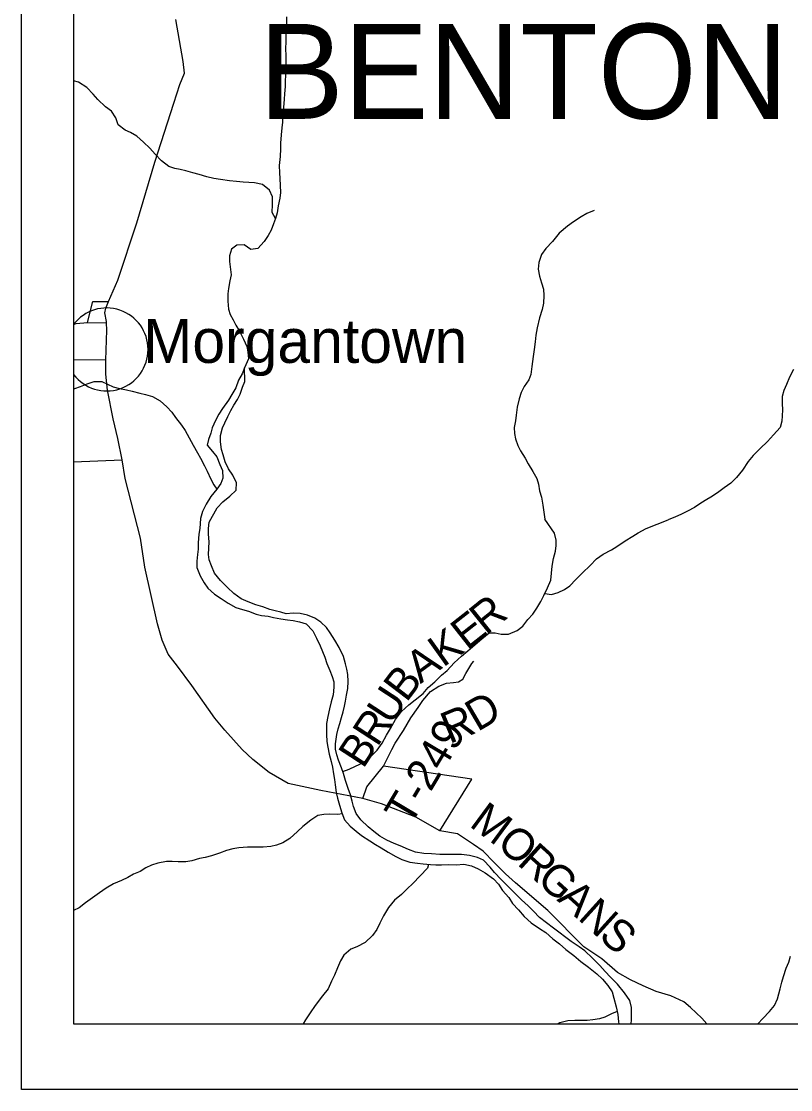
# Model space of a CAD drawing. Extents: x 0 to 34, y 0 to 22.
# Drawn here: x 2.106 to 3.486, y 13.882 to 15.799 of the extents above; entities that cross this region are included whole.
import ezdxf

# ---------------------------------------------------------------- set-up
doc = ezdxf.new("R2010")
doc.units = 0
for name, color, linetype in [('Default', 7, 'Continuous'), ('GM_X_County_Road', 7, 'Continuous'), ('GM_X_County_Road_Text', 7, 'Continuous'), ('GM_X_Minor_River', 7, 'Continuous'), ('GM_X_Township_Road', 7, 'Continuous'), ('GM_X_Township_Road_Text', 7, 'Continuous'), ('GM_X_Township_Text', 7, 'Continuous'), ('GM_X_Unincorporated_Location', 7, 'Continuous'), ('GM_X_Unincorporated_Text', 7, 'Continuous'), ('SH_Cut_Line', 7, 'Continuous')]:
    doc.layers.add(name, color=color, linetype=linetype)

msp = doc.modelspace()

# ---------------------------------------------------------------- linework, layer by layer
at = {"layer": 'Default'}
msp.add_lwpolyline([(9.087, 13.8822), (2.1062, 13.8822), (2.1062, 20.9054), (9.087, 20.9054)], close=True, dxfattribs=at)
msp.add_lwpolyline([(2.2, 19.4329), (2.2, 14), (4.485, 14)], dxfattribs=at)
at = {"layer": 'GM_X_County_Road'}
msp.add_line((2.2577, 15.1912), (2.2, 15.1918), dxfattribs=at)
msp.add_lwpolyline([(3.3359, 14), (3.3268, 14.0106), (3.3065, 14.0298), (3.2945, 14.0395), (3.2711, 14.0504), (3.2447, 14.0583), (3.2217, 14.0684), (3.1987, 14.0793), (3.1753, 14.0921), (3.1472, 14.1168), (3.1152, 14.1384), (3.0503, 14.2034), (2.9925, 14.2535), (2.9749, 14.2696), (2.9546, 14.29), (2.9347, 14.31), (2.9174, 14.322), (2.8885, 14.3409), (2.8571, 14.3467), (2.8141, 14.371), (2.7522, 14.3953), (2.719, 14.4048), (2.6434, 14.419), (2.6101, 14.4262), (2.5848, 14.4318), (2.5505, 14.4512), (2.5215, 14.4747), (2.502, 14.4928), (2.471, 14.5274), (2.453, 14.5485), (2.4123, 14.6071), (2.3862, 14.642), (2.3697, 14.6634), (2.3586, 14.6886), (2.3502, 14.718), (2.3278, 14.8197), (2.32, 14.8715), (2.2924, 14.9786), (2.2872, 15.0122), (2.2791, 15.0506), (2.2708, 15.0861), (2.2607, 15.1371), (2.258, 15.166), (2.2577, 15.1912), (2.2594, 15.2447), (2.2589, 15.2582), (2.2588, 15.2603), (2.256, 15.2759), (2.2576, 15.2846), (2.2628, 15.2966), (2.2793, 15.3345), (2.3133, 15.4373), (2.3455, 15.5463), (2.3795, 15.6522), (2.3905, 15.6859), (2.3986, 15.7063), (2.3966, 15.7268), (2.3834, 15.8025)], dxfattribs=at)
at = {"layer": 'GM_X_Minor_River'}
msp.add_line((3.1776, 14.0036), (3.1782, 14), dxfattribs=at)
for points in [[(2.5821, 15.8073), (2.5817, 15.7971), (2.5809, 15.7849), (2.5805, 15.7735), (2.5805, 15.7629), (2.5801, 15.7496), (2.5805, 15.7378), (2.5805, 15.7172), (2.5801, 15.7024), (2.5797, 15.6918), (2.5793, 15.6823), (2.5782, 15.6689), (2.5774, 15.6591), (2.5763, 15.6442), (2.5755, 15.6317), (2.5748, 15.6184), (2.5736, 15.6077), (2.5725, 15.5956), (2.5713, 15.5807), (2.5709, 15.5701), (2.5702, 15.5568), (2.5686, 15.5404), (2.5694, 15.5275), (2.5698, 15.5172), (2.5705, 15.5047), (2.5709, 15.4918), (2.5697, 15.4819), (2.5671, 15.4678), (2.5648, 15.4553), (2.5621, 15.445), (2.5587, 15.4355), (2.5545, 15.4245), (2.5492, 15.415), (2.5416, 15.4039), (2.5303, 15.3914), (2.5177, 15.3899), (2.5056, 15.3982), (2.4927, 15.3975), (2.4829, 15.3903), (2.4794, 15.3781), (2.4794, 15.3682), (2.4809, 15.3587), (2.4824, 15.3443), (2.4802, 15.3336), (2.4775, 15.3199), (2.4767, 15.31), (2.4767, 15.2967), (2.4775, 15.2827), (2.4805, 15.2728), (2.4862, 15.2633), (2.4911, 15.2538), (2.4976, 15.2431), (2.5048, 15.2287), (2.5104, 15.2157), (2.5127, 15.2059), (2.5135, 15.1937), (2.5066, 15.1773)], [(2.5621, 15.445), (2.5561, 15.456), (2.5569, 15.4705), (2.5565, 15.4842), (2.5512, 15.4963), (2.539, 15.5062), (2.5243, 15.5093), (2.514, 15.51), (2.5042, 15.5104), (2.492, 15.5115), (2.4795, 15.5127), (2.4632, 15.515), (2.4514, 15.5172), (2.4389, 15.5203), (2.4253, 15.5245), (2.4139, 15.5275), (2.401, 15.5309), (2.3908, 15.5332), (2.3813, 15.5351), (2.3707, 15.5385), (2.3578, 15.5488), (2.346, 15.561), (2.3366, 15.5712), (2.3256, 15.5823), (2.3134, 15.5929), (2.3017, 15.5998), (2.2922, 15.6039), (2.2797, 15.6131), (2.2755, 15.6256), (2.2679, 15.6378), (2.2573, 15.6454), (2.2433, 15.6587), (2.235, 15.6682), (2.2236, 15.6804), (2.2088, 15.6899), (2.2, 15.692)], [(3.1337, 15.4599), (3.1208, 15.4542), (3.1105, 15.4485), (3.0969, 15.4393), (3.0859, 15.4317), (3.0711, 15.4188), (3.0589, 15.4043), (3.0472, 15.3914), (3.0392, 15.3808), (3.0343, 15.3663), (3.0335, 15.3542), (3.0358, 15.3416), (3.0395, 15.3298), (3.0426, 15.3184), (3.0437, 15.3074), (3.0426, 15.2933), (3.0403, 15.2819), (3.0357, 15.2671), (3.0312, 15.2492), (3.0289, 15.2359), (3.0277, 15.2241), (3.0262, 15.2101), (3.0243, 15.1975), (3.022, 15.18), (3.0201, 15.1656), (3.0167, 15.1557), (3.0084, 15.1439), (3.0027, 15.1333), (2.9992, 15.1215), (2.9958, 15.1067), (2.9939, 15.0926), (2.9924, 15.0823), (2.9901, 15.0702), (2.9909, 15.0595), (2.9924, 15.05), (2.9965, 15.0382), (3.0015, 15.0287), (3.0098, 15.0154), (3.0151, 15.0051), (3.0238, 14.9915), (3.0306, 14.9785), (3.0337, 14.9683), (3.0359, 14.9569), (3.039, 14.9451), (3.0416, 14.931), (3.0435, 14.9181), (3.0454, 14.9055)], [(2.5066, 15.1773), (2.5021, 15.1667), (2.496, 15.1549), (2.4911, 15.1416), (2.4839, 15.1294), (2.4778, 15.1192), (2.4672, 15.1043), (2.4607, 15.0941), (2.4542, 15.0827), (2.4485, 15.0697), (2.4459, 15.0602), (2.4421, 15.0485), (2.4394, 15.0386), (2.4493, 15.0272), (2.4569, 15.0178), (2.4621, 15.0039), (2.4671, 14.9929), (2.4675, 14.9796), (2.464, 14.9698), (2.4568, 14.9599), (2.4462, 14.9462), (2.4379, 14.9329), (2.4314, 14.9196), (2.4276, 14.907)], [(2.443, 14.9003), (2.4572, 14.9264), (2.4674, 14.9371), (2.48, 14.9473), (2.4917, 14.958), (2.4921, 14.9709), (2.4853, 14.9846), (2.4777, 14.996), (2.472, 15.0089), (2.4682, 15.0211), (2.4652, 15.031), (2.4637, 15.0443), (2.4637, 15.0557), (2.4671, 15.0694), (2.4709, 15.0789), (2.4766, 15.0903), (2.4819, 15.1005), (2.4876, 15.1101), (2.4937, 15.1207), (2.4986, 15.1302), (2.5028, 15.1424), (2.507, 15.153), (2.5066, 15.1773)], [(3.4912, 15.1743), (3.4843, 15.1603), (3.4786, 15.1477), (3.4737, 15.1367), (3.471, 15.1257), (3.471, 15.1131), (3.4714, 15.1017), (3.471, 15.0911), (3.4702, 15.0816), (3.4672, 15.0705), (3.4554, 15.0572), (3.4444, 15.0454), (3.4315, 15.0325), (3.419, 15.0203), (3.4099, 15.0093), (3.4, 14.9937), (3.389, 14.9804), (3.3788, 14.9705), (3.3666, 14.9618), (3.3572, 14.955), (3.3458, 14.9473), (3.3329, 14.939), (3.3234, 14.9333), (3.3139, 14.9268), (3.301, 14.92), (3.2892, 14.9143), (3.2798, 14.9101), (3.2665, 14.9044)], [(2.2, 15.1404), (2.2024, 15.1405), (2.2123, 15.1439), (2.2244, 15.1485), (2.2366, 15.1526), (2.2506, 15.1526), (2.2711, 15.1435), (2.2821, 15.1401), (2.2946, 15.1378), (2.3052, 15.1355), (2.3185, 15.1321), (2.3287, 15.1294), (2.3412, 15.126), (2.3553, 15.118), (2.3674, 15.1074), (2.3761, 15.0975), (2.3829, 15.088), (2.3936, 15.0747), (2.4, 15.0648), (2.4072, 15.0519), (2.4144, 15.0386), (2.422, 15.0249), (2.4273, 15.015), (2.4349, 15.0013), (2.4394, 14.9918), (2.4462, 14.9774), (2.4515, 14.9675), (2.4568, 14.9599)], [(2.4276, 14.907), (2.4263, 14.8893), (2.4244, 14.8791), (2.4236, 14.8635), (2.4232, 14.8521), (2.4224, 14.8426), (2.4212, 14.8305), (2.4212, 14.8191), (2.4272, 14.8043), (2.434, 14.7917), (2.4407, 14.7818), (2.4524, 14.7712), (2.4645, 14.7635), (2.477, 14.7552), (2.491, 14.7475), (2.5027, 14.7437), (2.5136, 14.7406), (2.5272, 14.7356), (2.5371, 14.733), (2.5488, 14.7318), (2.5586, 14.7291), (2.5719, 14.7268), (2.5836, 14.7252), (2.5938, 14.7237), (2.6052, 14.7217), (2.6173, 14.7179), (2.629, 14.7057), (2.6357, 14.6924), (2.6421, 14.6787), (2.6466, 14.6681), (2.6504, 14.6582), (2.6541, 14.6468), (2.6594, 14.6343), (2.6639, 14.6236), (2.6665, 14.6141), (2.6668, 14.6042), (2.6653, 14.5906), (2.6622, 14.5781), (2.6591, 14.5652), (2.6561, 14.5519), (2.6537, 14.539), (2.6533, 14.5295), (2.6533, 14.5196), (2.6544, 14.5071), (2.6559, 14.4965), (2.6581, 14.4843), (2.6618, 14.471), (2.6645, 14.4611), (2.6663, 14.449), (2.6682, 14.4387), (2.6689, 14.4292), (2.6707, 14.4156), (2.673, 14.4053), (2.6767, 14.3924), (2.6808, 14.3787), (2.6861, 14.3665), (2.6963, 14.3548), (2.7065, 14.346), (2.7163, 14.3384), (2.731, 14.3288), (2.7412, 14.322), (2.7518, 14.3159), (2.7642, 14.3082), (2.7782, 14.3006), (2.7888, 14.2952), (2.8032, 14.2906), (2.8168, 14.2883), (2.827, 14.2872), (2.8399, 14.286), (2.8497, 14.2856), (2.8599, 14.2855), (2.8732, 14.2863), (2.886, 14.2858), (2.9, 14.2866), (2.9136, 14.2835), (2.9257, 14.2785), (2.9382, 14.2713), (2.9529, 14.2602), (2.962, 14.2507), (2.9691, 14.2396), (2.9808, 14.2267), (2.9872, 14.2164), (2.9978, 14.205), (3.008, 14.1928), (3.0208, 14.1814), (3.0355, 14.1711), (3.0468, 14.1642), (3.0597, 14.1528), (3.0718, 14.1437), (3.0831, 14.1338), (3.0974, 14.1231), (3.1099, 14.112), (3.1238, 14.1021), (3.1386, 14.0899), (3.1484, 14.0804), (3.1585, 14.069), (3.1657, 14.0576), (3.1687, 14.0466), (3.1732, 14.031), (3.1762, 14.0169), (3.1776, 14.0036)], [(3.2, 14), (3.2004, 14.0074), (3.2008, 14.0195), (3.2008, 14.0298), (3.1974, 14.0423), (3.1884, 14.056), (3.1756, 14.0712), (3.1631, 14.0842), (3.1537, 14.0941), (3.1439, 14.1051), (3.1307, 14.1184), (3.1171, 14.1314), (3.1066, 14.1382), (3.0926, 14.1482), (3.0828, 14.155), (3.0703, 14.1646), (3.0605, 14.1722), (3.048, 14.1817), (3.0356, 14.1909), (3.025, 14.2027), (3.0156, 14.2122), (3.0035, 14.2225), (2.9782, 14.248), (2.9669, 14.259), (2.9552, 14.2716), (2.9469, 14.2811), (2.9349, 14.2937), (2.9243, 14.2986), (2.9099, 14.3025), (2.8959, 14.304), (2.8566, 14.3041), (2.8418, 14.3053), (2.8282, 14.3061), (2.8134, 14.3081), (2.8006, 14.3131), (2.7859, 14.3195), (2.7749, 14.3238), (2.7617, 14.3299), (2.7492, 14.3371), (2.7383, 14.3451), (2.7284, 14.3539), (2.7149, 14.3661), (2.7066, 14.3779), (2.7021, 14.3904), (2.6998, 14.3999), (2.6968, 14.4109), (2.6927, 14.4227), (2.6878, 14.4368), (2.6841, 14.4493), (2.6807, 14.4596), (2.6751, 14.4733), (2.6721, 14.4831), (2.6699, 14.4934), (2.6699, 14.5029), (2.6718, 14.5192), (2.6745, 14.5298), (2.6772, 14.5393), (2.6807, 14.5499), (2.6833, 14.5602), (2.6856, 14.57), (2.6879, 14.5795), (2.6895, 14.5898), (2.6918, 14.6019), (2.6922, 14.6144), (2.6919, 14.6269), (2.69, 14.6368), (2.6874, 14.6463), (2.6841, 14.6592), (2.6762, 14.6756), (2.6686, 14.6885), (2.6604, 14.7018), (2.6536, 14.7117), (2.6434, 14.7209), (2.6324, 14.7281), (2.6196, 14.7338), (2.6063, 14.7365), (2.5939, 14.7373), (2.5814, 14.7359), (2.5715, 14.7389), (2.5617, 14.7412), (2.5519, 14.7439), (2.5394, 14.7485), (2.5269, 14.7523), (2.5133, 14.7573), (2.5005, 14.7627), (2.4873, 14.7726), (2.4759, 14.7833), (2.4635, 14.7958), (2.4529, 14.8091), (2.4473, 14.8221), (2.4432, 14.8327), (2.4417, 14.8426), (2.4425, 14.8536), (2.4429, 14.865), (2.4418, 14.879), (2.4419, 14.8893), (2.443, 14.9003)], [(2.6829, 14.4531), (2.694, 14.4573), (2.7057, 14.4625), (2.7186, 14.4686), (2.7311, 14.4784), (2.7444, 14.4913), (2.7532, 14.5038), (2.7612, 14.5185), (2.7684, 14.5303), (2.7772, 14.5466), (2.7882, 14.5606), (2.8011, 14.5727), (2.8128, 14.5814), (2.8269, 14.5931), (2.836, 14.6037), (2.8481, 14.6139), (2.8599, 14.6257), (2.8702, 14.634), (2.8823, 14.648), (2.896, 14.6601), (2.907, 14.6696), (2.9199, 14.6805), (2.9324, 14.6911), (2.9453, 14.7017), (2.9563, 14.7021), (2.9669, 14.6997), (2.9798, 14.6993), (2.9957, 14.7061), (3.0055, 14.7141), (3.015, 14.7258), (3.0234, 14.7356), (3.0306, 14.7462), (3.0379, 14.758), (3.0432, 14.7686), (3.05, 14.7826), (3.0558, 14.7963), (3.0573, 14.8088), (3.0581, 14.8213), (3.0608, 14.835), (3.0643, 14.8483), (3.0654, 14.8585), (3.0655, 14.8684), (3.0625, 14.8805), (3.0454, 14.9055)], [(3.0452, 14.7726), (3.0572, 14.7708), (3.0689, 14.7742), (3.0803, 14.7795), (3.0902, 14.7863), (3.1008, 14.7973), (3.1126, 14.8094), (3.1263, 14.8226), (3.1376, 14.8347), (3.1498, 14.8427), (3.1646, 14.851), (3.1744, 14.857), (3.1892, 14.8668), (3.2029, 14.8755), (3.2124, 14.8812), (3.2271, 14.8891), (3.2665, 14.9044)], [(2.6816, 14.377), (2.674, 14.3761), (2.6593, 14.3765), (2.6487, 14.3758), (2.6381, 14.3739), (2.6252, 14.366), (2.6111, 14.3543), (2.6016, 14.3452), (2.588, 14.3327), (2.5754, 14.3248), (2.5637, 14.321), (2.5535, 14.3187), (2.5402, 14.3173), (2.5118, 14.3174), (2.4963, 14.3163), (2.4853, 14.3144), (2.4744, 14.311), (2.4615, 14.3065), (2.4471, 14.302), (2.4357, 14.299), (2.4259, 14.2967), (2.4118, 14.293), (2.4012, 14.2908), (2.3876, 14.2908), (2.3766, 14.2916), (2.3664, 14.2916), (2.3509, 14.2886), (2.3395, 14.2849), (2.3293, 14.2803), (2.3191, 14.2739), (2.3073, 14.2686), (2.2971, 14.263), (2.2857, 14.2577), (2.2717, 14.2513), (2.2584, 14.2437), (2.2463, 14.2351), (2.2337, 14.2264), (2.2212, 14.2173), (2.2098, 14.2086), (2.2, 14.2037)], [(2.8367, 14.2863), (2.8345, 14.2795), (2.8216, 14.2659), (2.8083, 14.2523), (2.7985, 14.2428), (2.7878, 14.2322), (2.7757, 14.222), (2.765, 14.2088), (2.7559, 14.194), (2.7491, 14.1811), (2.7437, 14.1697), (2.7361, 14.1587), (2.7228, 14.1463), (2.708, 14.1387), (2.6974, 14.1342), (2.6845, 14.1232), (2.6784, 14.1134), (2.6731, 14.1009), (2.6678, 14.0876), (2.6628, 14.0766), (2.6563, 14.063), (2.6464, 14.0508), (2.6331, 14.0334), (2.6244, 14.0198), (2.616, 14.0073), (2.612, 14)], [(3.4274, 14), (3.4365, 14.0097), (3.4479, 14.0225), (3.4574, 14.0331), (3.4624, 14.0453), (3.4674, 14.0631), (3.4704, 14.0752), (3.4731, 14.0851), (3.4781, 14.1003), (3.4827, 14.1109), (3.4861, 14.1215)], [(3.175, 14.0225), (3.1648, 14.0185), (3.1527, 14.0124), (3.1432, 14.0094), (3.1311, 14.0072), (3.1209, 14.0065), (3.1103, 14.0061), (3.0993, 14.0062), (3.0864, 14.0058), (3.072, 14.0021), (3.0693, 14)]]:
    msp.add_lwpolyline(points, dxfattribs=at)
at = {"layer": 'GM_X_Township_Road'}
for p, q in [((2.2251, 15.2589), (2.2347, 15.2966)), ((2.2347, 15.2966), (2.2628, 15.2966)), ((2.2, 15.2554), (2.2, 15.1652)), ((2.2, 15.0085), (2.2872, 15.0122))]:
    msp.add_line(p, q, dxfattribs=at)
for points in [[(2.2, 15.2548), (2.2046, 15.2567), (2.2251, 15.2589), (2.2589, 15.2582)], [(2.7709, 14.4924), (2.7769, 14.5041), (2.7919, 14.5268), (2.8051, 14.5494), (2.8178, 14.5679), (2.8266, 14.5807), (2.8401, 14.5965), (2.8549, 14.6062), (2.8686, 14.6114), (2.8812, 14.6128), (2.8906, 14.6142), (2.8983, 14.619), (2.9033, 14.6289), (2.914, 14.647), (2.918, 14.6508)], [(2.719, 14.4048), (2.726, 14.4253), (2.7556, 14.4628), (2.7709, 14.4924)], [(2.8571, 14.3467), (2.9145, 14.4391), (2.7556, 14.4628)]]:
    msp.add_lwpolyline(points, dxfattribs=at)
msp.add_arc((2.2592, 15.2103), 0.0744, 217.3185, 142.6815, dxfattribs=at)
at = {"layer": 'GM_X_Unincorporated_Location'}
msp.add_line((2.2592, 15.2103), (2.2592, 15.2103), dxfattribs=at)
at = {"layer": 'SH_Cut_Line'}
msp.add_lwpolyline([(2.2, 19.4329), (2.2, 14), (9, 14), (9, 18.8941), (8.8762, 18.9027), (8.0305, 18.9725), (6.8442, 19.0679), (6.226, 19.1161), (5.8337, 19.1499), (5.3224, 19.1939), (5.1554, 19.2083), (4.831, 19.2363), (4.7641, 19.2419), (3.1893, 19.3592), (2.7961, 19.3885)], close=True, dxfattribs=at)

# ---------------------------------------------------------------- texts
at = {"layer": 'GM_X_County_Road_Text'}
for s, rotation, p in [('M', 323.5826, (2.9078, 14.3559)), ('O', 318.7195, (2.9565, 14.3201)), ('R', 317.888, (2.9939, 14.2872)), ('G', 317.8809, (3.0285, 14.2559)), ('A', 317.8798, (3.0656, 14.2224)), ('N', 317.8824, (3.1027, 14.1889)), ('S', 317.8839, (3.1398, 14.1553))]:
    msp.add_text(s, height=0.0568, rotation=rotation, dxfattribs=at).set_placement(p)
at = {"layer": 'GM_X_Township_Road_Text'}
for s, height, rotation, p in [('R', 0.0568, 38.9089, (2.9395, 14.6964)), ('E', 0.0568, 38.1815, (2.9055, 14.6696)), ('K', 0.0568, 35.511, (2.8625, 14.6389)), ('A', 0.0568, 35.9002, (2.8221, 14.6096)), ('B', 0.0568, 52.6649, (2.7969, 14.5756)), ('U', 0.0568, 56.8141, (2.7702, 14.5346)), ('D', 0.0568, 30.3838, (2.9244, 14.5236)), ('R', 0.0568, 22.7327, (2.8741, 14.5019)), ('R', 0.0568, 56.9213, (2.7447, 14.4955)), ('T-249', 0.05682, 59.261, (2.8037, 14.3535)), ('B', 0.0568, 56.9172, (2.7192, 14.4564))]:
    msp.add_text(s, height=height, rotation=rotation, dxfattribs=at).set_placement(p)
at = {"layer": 'GM_X_Township_Text'}
msp.add_text('BENTON', height=0.17045, rotation=0, dxfattribs=at).set_placement((2.5324, 15.6241))
at = {"layer": 'GM_X_Unincorporated_Text'}
msp.add_text('Morgantown', height=0.07898, rotation=0, dxfattribs=at).set_placement((2.3249, 15.1862))

doc.saveas('drawing.dxf')
